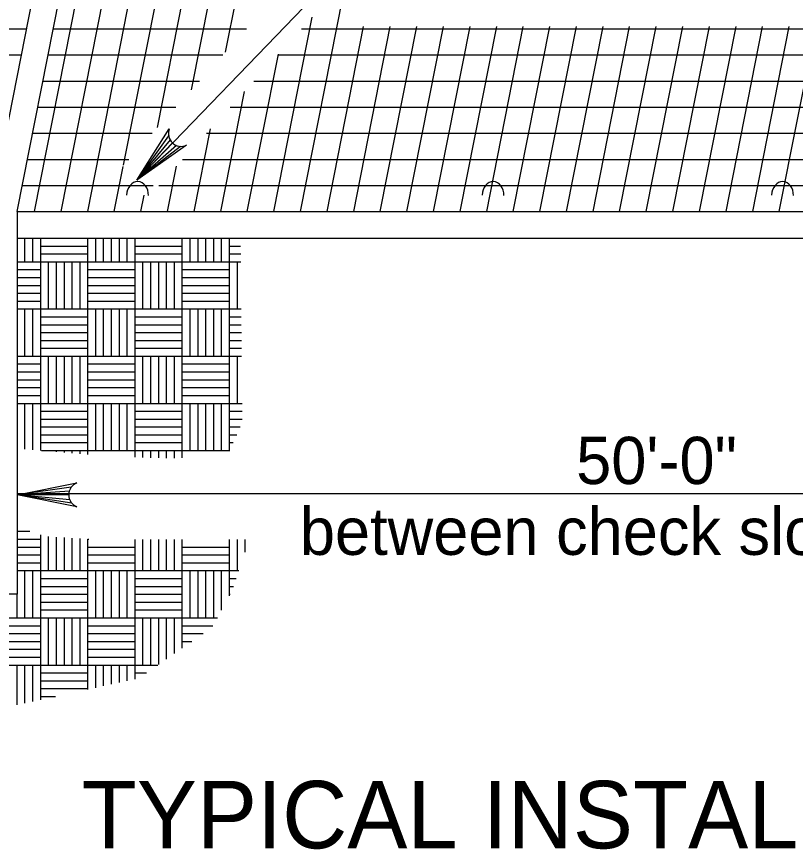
# Model space of a CAD drawing. Extents: x 1083.1 to 1117.1, y 719.4 to 741.4.
# Drawn here: x 1098.974 to 1101.283, y 725.987 to 728.456 of the extents above; entities that cross this region are included whole.
import ezdxf

# ---------------------------------------------------------------- set-up
doc = ezdxf.new("R2010")
doc.units = 0
doc.layers.add('ST_Details', color=7, linetype='Continuous')
doc.layers.add('ST_Text', color=7, linetype='Continuous')

msp = doc.modelspace()

# ---------------------------------------------------------------- linework, layer by layer
at = {"layer": 'ST_Details'}
for p, q in [((1098.8968, 727.8781), (1099.4078, 730.4631)), ((1098.9756, 727.8781), (1099.4567, 730.3113)), ((1099.0271, 727.8781), (1099.4885, 730.2124)), ((1099.106, 727.8781), (1099.5373, 730.0606)), ((1099.2303, 728.1086), (1099.5156, 729.5517)), ((1099.4928, 728.2392), (1099.6202, 728.8837)), ((1099.5938, 728.3509), (1099.7019, 728.8982)), ((1099.3918, 728.1272), (1099.5393, 728.8734)), ((1099.2909, 728.0156), (1099.4496, 728.8163)), ((1100.0671, 728.734), (1099.3303, 727.9711)), ((1099.8158, 727.8781), (1099.9516, 728.5652)), ((1099.7369, 727.8781), (1099.8509, 728.4548)), ((1097.8579, 728.4197), (1099.0034, 728.4197)), ((1099.0827, 728.4197), (1099.3802, 728.4197)), ((1099.3806, 728.4197), (1099.6558, 728.4197)), ((1099.8189, 728.4197), (1101.6582, 728.4197)), ((1099.8947, 727.8781), (1100.0031, 728.4267)), ((1099.9736, 727.8781), (1100.082, 728.4267)), ((1100.0524, 727.8781), (1100.1609, 728.4267)), ((1100.1313, 727.8781), (1100.2398, 728.4267)), ((1100.2102, 727.8781), (1100.3187, 728.4267)), ((1100.2891, 727.8781), (1100.3976, 728.4267)), ((1100.368, 727.8781), (1100.4764, 728.4267)), ((1100.4468, 727.8781), (1100.5553, 728.4267)), ((1100.5258, 727.8781), (1100.6342, 728.4267)), ((1100.6046, 727.8781), (1100.713, 728.4267)), ((1100.6835, 727.8781), (1100.7919, 728.4267)), ((1100.7623, 727.8781), (1100.8708, 728.4267)), ((1100.8413, 727.8781), (1100.9497, 728.4267)), ((1100.9201, 727.8781), (1101.0286, 728.4267)), ((1100.999, 727.8781), (1101.1074, 728.4267)), ((1101.0779, 727.8781), (1101.1863, 728.4267)), ((1101.1568, 727.8781), (1101.2652, 728.4267)), ((1101.2357, 727.8781), (1101.3441, 728.4267)), ((1097.8426, 728.3423), (1098.9881, 728.3423)), ((1099.0674, 728.3423), (1099.3916, 728.3423)), ((1099.3729, 728.3423), (1099.586, 728.3423)), ((1099.6581, 727.8781), (1099.7503, 728.3443)), ((1099.7484, 728.3423), (1101.6429, 728.3423)), ((1099.0521, 728.265), (1099.3727, 728.265)), ((1099.3709, 728.265), (1099.5162, 728.265)), ((1099.6779, 728.265), (1101.6276, 728.265)), ((1099.5792, 727.8781), (1099.6495, 728.2337)), ((1099.0368, 728.1876), (1099.3764, 728.1876)), ((1099.3693, 728.1876), (1099.4463, 728.1876)), ((1099.6074, 728.1876), (1101.6123, 728.1876)), ((1099.5003, 727.8781), (1099.5488, 728.1232)), ((1099.0215, 728.1102), (1099.3764, 728.1102)), ((1099.1848, 727.8781), (1099.2305, 728.1092)), ((1099.4248, 728.1024), (1099.3303, 727.9711)), ((1099.429, 728.0908), (1099.3303, 727.9711)), ((1099.5368, 728.1102), (1101.5971, 728.1102)), ((1099.436, 728.0818), (1099.3303, 727.9711)), ((1099.4484, 728.0739), (1099.3303, 727.9711)), ((1099.4602, 728.0712), (1099.3303, 727.9711)), ((1099.0062, 728.0328), (1099.3065, 728.0328)), ((1099.4663, 728.0328), (1101.5818, 728.0328)), ((1099.2637, 727.8781), (1099.2901, 728.0113)), ((1099.4214, 727.8781), (1099.448, 728.0127)), ((1098.9909, 727.9555), (1099.3792, 727.9555)), ((1099.3958, 727.9555), (1101.5665, 727.9555)), ((1099.3425, 727.8781), (1099.3521, 727.9266)), ((1098.9756, 727.8781), (1098.9756, 726.7435)), ((1098.9756, 727.8781), (1101.5512, 727.8781)), ((1098.9756, 727.7992), (1101.5512, 727.7992)), ((1098.9989, 727.7293), (1098.9989, 727.7992)), ((1099.0223, 727.7293), (1099.0223, 727.7992)), ((1099.0456, 727.1698), (1099.0456, 727.7992)), ((1099.0456, 727.7992), (1099.1855, 727.7992)), ((1099.1855, 727.1582), (1099.1855, 727.7992)), ((1099.2088, 727.7293), (1099.2088, 727.7992)), ((1099.2322, 727.7293), (1099.2322, 727.7992)), ((1099.2555, 727.7293), (1099.2555, 727.7992)), ((1099.2788, 727.7293), (1099.2788, 727.7992)), ((1099.3022, 727.7293), (1099.3022, 727.7992)), ((1099.3254, 727.1497), (1099.3254, 727.7992)), ((1099.3254, 727.7992), (1099.4654, 727.7992)), ((1099.4654, 727.1476), (1099.4654, 727.7992)), ((1099.4888, 727.7293), (1099.4888, 727.7992)), ((1099.512, 727.7293), (1099.512, 727.7992)), ((1099.5353, 727.7293), (1099.5353, 727.7992)), ((1099.5587, 727.7293), (1099.5587, 727.7992)), ((1099.582, 727.7293), (1099.582, 727.7992)), ((1099.6053, 727.1676), (1099.6053, 727.7992)), ((1099.6053, 727.7992), (1099.6382, 727.7992)), ((1099.0456, 727.7759), (1099.1855, 727.7759)), ((1099.3254, 727.7759), (1099.4654, 727.7759)), ((1099.6053, 727.7759), (1099.6383, 727.7759)), ((1099.0456, 727.7526), (1099.1855, 727.7526)), ((1099.3254, 727.7526), (1099.4654, 727.7526)), ((1099.6053, 727.7526), (1099.6386, 727.7526)), ((1098.9756, 727.7293), (1099.6388, 727.7293)), ((1099.0689, 727.5893), (1099.0689, 727.7293)), ((1099.0923, 727.5893), (1099.0923, 727.7293)), ((1099.1156, 727.5893), (1099.1156, 727.7293)), ((1099.1389, 727.5893), (1099.1389, 727.7293)), ((1099.1622, 727.5893), (1099.1622, 727.7293)), ((1099.3488, 727.5893), (1099.3488, 727.7293)), ((1099.3721, 727.5893), (1099.3721, 727.7293)), ((1099.3954, 727.5893), (1099.3954, 727.7293)), ((1099.4188, 727.5893), (1099.4188, 727.7293)), ((1099.4421, 727.5893), (1099.4421, 727.7293)), ((1099.6287, 727.5893), (1099.6287, 727.7293)), ((1098.9756, 727.706), (1099.0456, 727.706)), ((1099.1855, 727.706), (1099.2555, 727.706)), ((1099.2555, 727.706), (1099.3254, 727.706)), ((1099.4654, 727.706), (1099.5353, 727.706)), ((1099.5353, 727.706), (1099.6053, 727.706)), ((1098.9756, 727.6827), (1099.0456, 727.6827)), ((1099.1855, 727.6827), (1099.2555, 727.6827)), ((1099.2555, 727.6827), (1099.3254, 727.6827)), ((1099.4654, 727.6827), (1099.5353, 727.6827)), ((1099.5353, 727.6827), (1099.6053, 727.6827)), ((1098.9756, 727.6593), (1099.0456, 727.6593)), ((1099.1855, 727.6593), (1099.2555, 727.6593)), ((1099.2555, 727.6593), (1099.3254, 727.6593)), ((1099.4654, 727.6593), (1099.5353, 727.6593)), ((1099.5353, 727.6593), (1099.6053, 727.6593)), ((1098.9756, 727.636), (1099.0456, 727.636)), ((1099.1855, 727.636), (1099.2555, 727.636)), ((1099.2555, 727.636), (1099.3254, 727.636)), ((1099.4654, 727.636), (1099.5353, 727.636)), ((1099.5353, 727.636), (1099.6053, 727.636)), ((1098.9756, 727.6127), (1099.0456, 727.6127)), ((1099.1855, 727.6127), (1099.2555, 727.6127)), ((1099.2555, 727.6127), (1099.3254, 727.6127)), ((1099.4654, 727.6127), (1099.5353, 727.6127)), ((1099.5353, 727.6127), (1099.6053, 727.6127)), ((1098.9756, 727.5893), (1099.64, 727.5893)), ((1098.9989, 727.5194), (1098.9989, 727.5893)), ((1099.0223, 727.5194), (1099.0223, 727.5893)), ((1099.2088, 727.5194), (1099.2088, 727.5893)), ((1099.2322, 727.5194), (1099.2322, 727.5893)), ((1099.2555, 727.5194), (1099.2555, 727.5893)), ((1099.2788, 727.5194), (1099.2788, 727.5893)), ((1099.3022, 727.5194), (1099.3022, 727.5893)), ((1099.4888, 727.5194), (1099.4888, 727.5893)), ((1099.512, 727.5194), (1099.512, 727.5893)), ((1099.5353, 727.5194), (1099.5353, 727.5893)), ((1099.5587, 727.5194), (1099.5587, 727.5893)), ((1099.582, 727.5194), (1099.582, 727.5893)), ((1099.0456, 727.5661), (1099.1855, 727.5661)), ((1099.3254, 727.5661), (1099.4654, 727.5661)), ((1099.6053, 727.5661), (1099.6403, 727.5661)), ((1099.0456, 727.5427), (1099.1855, 727.5427)), ((1099.3254, 727.5427), (1099.4654, 727.5427)), ((1099.6053, 727.5427), (1099.6404, 727.5427)), ((1098.9989, 727.4494), (1098.9989, 727.5194)), ((1099.0223, 727.4494), (1099.0223, 727.5194)), ((1099.0456, 727.5194), (1099.1855, 727.5194)), ((1099.2088, 727.4494), (1099.2088, 727.5194)), ((1099.2322, 727.4494), (1099.2322, 727.5194)), ((1099.2555, 727.4494), (1099.2555, 727.5194)), ((1099.2788, 727.4494), (1099.2788, 727.5194)), ((1099.3022, 727.4494), (1099.3022, 727.5194)), ((1099.3254, 727.5194), (1099.4654, 727.5194)), ((1099.4888, 727.4494), (1099.4888, 727.5194)), ((1099.512, 727.4494), (1099.512, 727.5194)), ((1099.5353, 727.4494), (1099.5353, 727.5194)), ((1099.5587, 727.4494), (1099.5587, 727.5194)), ((1099.582, 727.4494), (1099.582, 727.5194)), ((1099.6053, 727.5194), (1099.6407, 727.5194)), ((1099.0456, 727.4961), (1099.1855, 727.4961)), ((1099.0456, 727.4727), (1099.1855, 727.4727)), ((1099.3254, 727.4961), (1099.4654, 727.4961)), ((1099.3254, 727.4727), (1099.4654, 727.4727)), ((1099.6053, 727.4961), (1099.6408, 727.4961)), ((1099.6053, 727.4727), (1099.6411, 727.4727)), ((1098.9756, 727.4494), (1099.6413, 727.4494)), ((1099.0689, 727.3095), (1099.0689, 727.4494)), ((1099.0923, 727.3095), (1099.0923, 727.4494)), ((1099.1156, 727.3095), (1099.1156, 727.4494)), ((1099.1389, 727.3095), (1099.1389, 727.4494)), ((1099.1622, 727.3095), (1099.1622, 727.4494)), ((1099.3488, 727.3095), (1099.3488, 727.4494)), ((1099.3721, 727.3095), (1099.3721, 727.4494)), ((1099.3954, 727.3095), (1099.3954, 727.4494)), ((1099.4188, 727.3095), (1099.4188, 727.4494)), ((1099.4421, 727.3095), (1099.4421, 727.4494)), ((1099.6287, 727.3095), (1099.6287, 727.4494)), ((1098.9756, 727.4262), (1099.0456, 727.4262)), ((1099.1855, 727.4262), (1099.2555, 727.4262)), ((1099.2555, 727.4262), (1099.3254, 727.4262)), ((1099.4654, 727.4262), (1099.5353, 727.4262)), ((1099.5353, 727.4262), (1099.6053, 727.4262)), ((1098.9756, 727.4028), (1099.0456, 727.4028)), ((1099.1855, 727.4028), (1099.2555, 727.4028)), ((1099.2555, 727.4028), (1099.3254, 727.4028)), ((1099.4654, 727.4028), (1099.5353, 727.4028)), ((1099.5353, 727.4028), (1099.6053, 727.4028)), ((1098.9756, 727.3795), (1099.0456, 727.3795)), ((1099.1855, 727.3795), (1099.2555, 727.3795)), ((1099.2555, 727.3795), (1099.3254, 727.3795)), ((1099.4654, 727.3795), (1099.5353, 727.3795)), ((1099.5353, 727.3795), (1099.6053, 727.3795)), ((1098.9756, 727.3562), (1099.0456, 727.3562)), ((1099.1855, 727.3562), (1099.2555, 727.3562)), ((1099.2555, 727.3562), (1099.3254, 727.3562)), ((1099.4654, 727.3562), (1099.5353, 727.3562)), ((1099.5353, 727.3562), (1099.6053, 727.3562)), ((1098.9756, 727.3328), (1099.0456, 727.3328)), ((1099.1855, 727.3328), (1099.2555, 727.3328)), ((1099.2555, 727.3328), (1099.3254, 727.3328)), ((1099.4654, 727.3328), (1099.5353, 727.3328)), ((1099.5353, 727.3328), (1099.6053, 727.3328)), ((1098.9756, 727.3095), (1099.6425, 727.3095)), ((1098.9989, 727.2396), (1098.9989, 727.3095)), ((1099.0223, 727.2396), (1099.0223, 727.3095)), ((1099.2088, 727.2396), (1099.2088, 727.3095)), ((1099.2322, 727.2396), (1099.2322, 727.3095)), ((1099.2555, 727.2396), (1099.2555, 727.3095)), ((1099.2788, 727.2396), (1099.2788, 727.3095)), ((1099.3022, 727.2396), (1099.3022, 727.3095)), ((1099.4888, 727.2396), (1099.4888, 727.3095)), ((1099.512, 727.2396), (1099.512, 727.3095)), ((1099.5353, 727.2396), (1099.5353, 727.3095)), ((1099.5587, 727.2396), (1099.5587, 727.3095)), ((1099.582, 727.2396), (1099.582, 727.3095)), ((1099.0456, 727.2862), (1099.1855, 727.2862)), ((1099.3254, 727.2862), (1099.4654, 727.2862)), ((1099.6053, 727.2862), (1099.6428, 727.2862)), ((1099.0456, 727.2629), (1099.1855, 727.2629)), ((1099.3254, 727.2629), (1099.4654, 727.2629)), ((1099.6053, 727.2629), (1099.6429, 727.2629)), ((1098.9989, 727.1737), (1098.9989, 727.2396)), ((1099.0223, 727.1717), (1099.0223, 727.2396)), ((1099.0456, 727.2396), (1099.1855, 727.2396)), ((1099.2088, 727.1696), (1099.2088, 727.2396)), ((1099.2322, 727.1696), (1099.2322, 727.2396)), ((1099.2555, 727.1696), (1099.2555, 727.2396)), ((1099.2788, 727.1696), (1099.2788, 727.2396)), ((1099.3022, 727.1696), (1099.3022, 727.2396)), ((1099.3254, 727.2396), (1099.4654, 727.2396)), ((1099.4888, 727.1696), (1099.4888, 727.2396)), ((1099.512, 727.1696), (1099.512, 727.2396)), ((1099.5353, 727.1696), (1099.5353, 727.2396)), ((1099.5587, 727.1696), (1099.5587, 727.2396)), ((1099.582, 727.1696), (1099.582, 727.2396)), ((1099.6053, 727.2396), (1099.6369, 727.2396)), ((1099.0456, 727.2162), (1099.1855, 727.2162)), ((1099.3254, 727.2162), (1099.4654, 727.2162)), ((1099.6053, 727.2162), (1099.6267, 727.2162)), ((1099.0456, 727.1929), (1099.1855, 727.1929)), ((1099.3254, 727.1929), (1099.4654, 727.1929)), ((1099.6053, 727.1929), (1099.6164, 727.1929)), ((1099.0483, 727.1696), (1099.6063, 727.1696)), ((1099.0689, 727.1679), (1099.0689, 727.1696)), ((1099.0923, 727.1659), (1099.0923, 727.1696)), ((1099.1156, 727.164), (1099.1156, 727.1696)), ((1099.1389, 727.1621), (1099.1389, 727.1696)), ((1099.1622, 727.1602), (1099.1622, 727.1696)), ((1099.3488, 727.1491), (1099.3488, 727.1696)), ((1099.3721, 727.1484), (1099.3721, 727.1696)), ((1099.3954, 727.1477), (1099.3954, 727.1696)), ((1099.4188, 727.1472), (1099.4188, 727.1696)), ((1099.4421, 727.1465), (1099.4421, 727.1696)), ((1099.1358, 727.0606), (1098.9756, 727.0382)), ((1099.1304, 727.0495), (1098.9756, 727.0382)), ((1098.9756, 727.0418), (1100.203, 727.0418)), ((1099.1288, 727.0382), (1098.9756, 727.0382)), ((1099.1316, 727.0238), (1098.9756, 727.0382)), ((1099.1378, 727.0134), (1098.9756, 727.0382)), ((1100.203, 727.0418), (1102.2743, 727.0418)), ((1098.9757, 726.9301), (1099.0134, 726.9301)), ((1098.9759, 726.9067), (1099.0456, 726.9067)), ((1099.0456, 726.7053), (1099.0456, 726.9199)), ((1099.0689, 726.8135), (1099.0689, 726.9147)), ((1099.0923, 726.8135), (1099.0923, 726.9132)), ((1099.1156, 726.8135), (1099.1156, 726.9116)), ((1099.1389, 726.8135), (1099.1389, 726.9101)), ((1099.1622, 726.8135), (1099.1622, 726.9085)), ((1099.1855, 726.7053), (1099.1855, 726.9069)), ((1099.1855, 726.9067), (1099.1883, 726.9067)), ((1099.3254, 726.7053), (1099.3254, 726.9056)), ((1099.3488, 726.8135), (1099.3488, 726.9056)), ((1099.3721, 726.8135), (1099.3721, 726.9056)), ((1099.3954, 726.8135), (1099.3954, 726.9056)), ((1099.4188, 726.8135), (1099.4188, 726.9056)), ((1099.4421, 726.8135), (1099.4421, 726.9056)), ((1099.4654, 726.7053), (1099.4654, 726.9056)), ((1099.6053, 726.7389), (1099.6053, 726.9056)), ((1099.6287, 726.8135), (1099.6287, 726.9056)), ((1099.652, 726.868), (1099.652, 726.9056)), ((1098.9761, 726.8834), (1099.0456, 726.8834)), ((1099.1855, 726.8834), (1099.2555, 726.8834)), ((1099.2555, 726.8834), (1099.3254, 726.8834)), ((1099.4654, 726.8834), (1099.5353, 726.8834)), ((1099.5353, 726.8834), (1099.6053, 726.8834)), ((1098.9763, 726.8602), (1099.0456, 726.8602)), ((1099.1855, 726.8602), (1099.2555, 726.8602)), ((1099.2555, 726.8602), (1099.3254, 726.8602)), ((1099.4654, 726.8602), (1099.5353, 726.8602)), ((1099.5353, 726.8602), (1099.6053, 726.8602)), ((1098.9765, 726.8368), (1099.0456, 726.8368)), ((1099.1855, 726.8368), (1099.2555, 726.8368)), ((1099.2555, 726.8368), (1099.3254, 726.8368)), ((1099.4654, 726.8368), (1099.5353, 726.8368)), ((1099.5353, 726.8368), (1099.6053, 726.8368)), ((1098.9768, 726.8135), (1099.6333, 726.8135)), ((1098.9989, 726.7435), (1098.9989, 726.8135)), ((1099.0223, 726.7435), (1099.0223, 726.8135)), ((1099.2088, 726.7435), (1099.2088, 726.8135)), ((1099.2322, 726.7435), (1099.2322, 726.8135)), ((1099.2555, 726.7435), (1099.2555, 726.8135)), ((1099.2788, 726.7435), (1099.2788, 726.8135)), ((1099.3022, 726.7435), (1099.3022, 726.8135)), ((1099.4888, 726.7435), (1099.4888, 726.8135)), ((1099.512, 726.7435), (1099.512, 726.8135)), ((1099.5353, 726.7435), (1099.5353, 726.8135)), ((1099.5587, 726.7435), (1099.5587, 726.8135)), ((1099.582, 726.7435), (1099.582, 726.8135)), ((1099.0456, 726.7902), (1099.1855, 726.7902)), ((1099.3254, 726.7902), (1099.4654, 726.7902)), ((1099.6053, 726.7902), (1099.6253, 726.7902)), ((1099.0456, 726.7668), (1099.1855, 726.7668)), ((1099.3254, 726.7668), (1099.4654, 726.7668)), ((1099.6053, 726.7668), (1099.6173, 726.7668)), ((1098.9756, 726.7435), (1098.6583, 726.7435)), ((1098.9756, 726.7053), (1098.9756, 726.7435)), ((1098.9989, 726.7053), (1098.9989, 726.7435)), ((1099.0223, 726.7053), (1099.0223, 726.7435)), ((1099.0456, 726.7435), (1099.1855, 726.7435)), ((1099.2088, 726.7053), (1099.2088, 726.7435)), ((1099.2322, 726.7053), (1099.2322, 726.7435)), ((1099.2555, 726.7053), (1099.2555, 726.7435)), ((1099.2788, 726.7053), (1099.2788, 726.7435)), ((1099.3022, 726.7053), (1099.3022, 726.7435)), ((1099.3254, 726.7435), (1099.4654, 726.7435)), ((1099.4888, 726.7053), (1099.4888, 726.7435)), ((1099.512, 726.7053), (1099.512, 726.7435)), ((1099.5353, 726.7053), (1099.5353, 726.7435)), ((1099.5587, 726.7053), (1099.5587, 726.7435)), ((1099.582, 726.7053), (1099.582, 726.7435)), ((1099.6053, 726.7435), (1099.6078, 726.7435)), ((1099.0456, 726.7202), (1099.1855, 726.7202)), ((1099.3254, 726.7202), (1099.4654, 726.7202)), ((1098.9756, 726.6736), (1098.9756, 726.7053)), ((1098.9989, 726.6736), (1098.9989, 726.7053)), ((1099.0223, 726.6736), (1099.0223, 726.7053)), ((1099.0456, 726.4307), (1099.0456, 726.7053)), ((1099.0456, 726.6969), (1099.1855, 726.6969)), ((1099.1855, 726.4613), (1099.1855, 726.7053)), ((1099.2088, 726.6736), (1099.2088, 726.7053)), ((1099.2322, 726.6736), (1099.2322, 726.7053)), ((1099.2555, 726.6736), (1099.2555, 726.7053)), ((1099.2788, 726.6736), (1099.2788, 726.7053)), ((1099.3022, 726.6736), (1099.3022, 726.7053)), ((1099.3254, 726.4921), (1099.3254, 726.7053)), ((1099.3254, 726.6969), (1099.4654, 726.6969)), ((1099.4654, 726.5839), (1099.4654, 726.7053)), ((1099.4888, 726.6736), (1099.4888, 726.7053)), ((1099.512, 726.6736), (1099.512, 726.7053)), ((1099.5353, 726.6736), (1099.5353, 726.7053)), ((1099.5587, 726.6736), (1099.5587, 726.7053)), ((1099.582, 726.6967), (1099.582, 726.7053)), ((1098.3023, 726.6736), (1099.5693, 726.6736)), ((1099.0689, 726.5337), (1099.0689, 726.6736)), ((1099.0923, 726.5337), (1099.0923, 726.6736)), ((1099.1156, 726.5337), (1099.1156, 726.6736)), ((1099.1389, 726.5337), (1099.1389, 726.6736)), ((1099.1622, 726.5337), (1099.1622, 726.6736)), ((1099.3488, 726.5337), (1099.3488, 726.6736)), ((1099.3721, 726.5337), (1099.3721, 726.6736)), ((1099.3954, 726.5352), (1099.3954, 726.6736)), ((1099.4188, 726.5515), (1099.4188, 726.6736)), ((1099.4421, 726.5677), (1099.4421, 726.6736)), ((1098.9057, 726.6502), (1098.9756, 726.6502)), ((1098.9756, 726.6502), (1099.0456, 726.6502)), ((1099.1855, 726.6502), (1099.2555, 726.6502)), ((1099.2555, 726.6502), (1099.3254, 726.6502)), ((1099.4654, 726.6502), (1099.5353, 726.6502)), ((1099.5353, 726.6502), (1099.5563, 726.6502)), ((1098.9057, 726.6269), (1098.9756, 726.6269)), ((1098.9756, 726.6269), (1099.0456, 726.6269)), ((1099.1855, 726.6269), (1099.2555, 726.6269)), ((1099.2555, 726.6269), (1099.3254, 726.6269)), ((1099.4654, 726.6269), (1099.5271, 726.6269)), ((1098.9057, 726.6036), (1098.9756, 726.6036)), ((1098.9756, 726.6036), (1099.0456, 726.6036)), ((1099.1855, 726.6036), (1099.2555, 726.6036)), ((1099.2555, 726.6036), (1099.3254, 726.6036)), ((1099.4654, 726.6036), (1099.4937, 726.6036)), ((1098.9057, 726.5802), (1098.9756, 726.5802)), ((1098.9756, 726.5802), (1099.0456, 726.5802)), ((1099.1855, 726.5802), (1099.2555, 726.5802)), ((1099.2555, 726.5802), (1099.3254, 726.5802)), ((1098.9057, 726.557), (1098.9756, 726.557)), ((1098.9756, 726.557), (1099.0456, 726.557)), ((1099.1855, 726.557), (1099.2555, 726.557)), ((1099.2555, 726.557), (1099.3254, 726.557)), ((1098.4618, 726.5337), (1099.3931, 726.5337)), ((1098.9756, 726.4637), (1098.9756, 726.5337)), ((1098.9989, 726.4637), (1098.9989, 726.5337)), ((1099.0223, 726.4637), (1099.0223, 726.5337)), ((1099.0456, 726.5103), (1099.1855, 726.5103)), ((1099.2088, 726.4665), (1099.2088, 726.5337)), ((1099.2322, 726.4716), (1099.2322, 726.5337)), ((1099.2555, 726.4767), (1099.2555, 726.5337)), ((1099.2788, 726.4818), (1099.2788, 726.5337)), ((1099.3022, 726.487), (1099.3022, 726.5337)), ((1099.3254, 726.5103), (1099.3596, 726.5103)), ((1099.0456, 726.487), (1099.1855, 726.487)), ((1098.9756, 726.4153), (1098.9756, 726.4637)), ((1098.9989, 726.4205), (1098.9989, 726.4637)), ((1099.0223, 726.4256), (1099.0223, 726.4637)), ((1099.0456, 726.4637), (1099.1855, 726.4637)), ((1099.0456, 726.4403), (1099.0898, 726.4403))]:
    msp.add_line(p, q, dxfattribs=at)
for points in [[(1099.4781, 728.0746), (1099.3303, 727.9711), (1099.4269, 728.1235)], [(1099.1526, 727.0028), (1098.9756, 727.0382), (1099.1526, 727.0736)]]:
    msp.add_lwpolyline(points, dxfattribs=at)
for centre, start, end in [((1099.4624, 728.1094), 158.3899, 294.216), ((1099.1669, 727.0382), 112.0878, 247.9139)]:
    msp.add_arc(centre, 0.0382, start, end, dxfattribs=at)
for centre in [(1099.3326, 727.9261), (1100.3867, 727.9261), (1101.2452, 727.9261)]:
    msp.add_ellipse(centre, major_axis=(0.001, 0.041), ratio=0.78812, start_param=4.7124, end_param=7.853992, dxfattribs=at)

# ---------------------------------------------------------------- texts
at = {"layer": 'ST_Text'}
for s, height, p in [('50\'-0"', 0.14, (1100.6333, 727.0702)), ('between check slots', 0.14, (1099.814, 726.8602)), ('TYPICAL INSTALLATION', 0.2, (1099.167, 725.9901))]:
    msp.add_text(s, height=height, dxfattribs=at).set_placement(p)

doc.saveas('drawing.dxf')
